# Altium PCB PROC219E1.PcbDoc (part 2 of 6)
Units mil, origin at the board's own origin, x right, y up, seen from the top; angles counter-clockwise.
Board outline 5354.33 x 5354.33 mil, 4 copper layers (Top Layer, Inner Layer 1, Inner Layer 2, Bottom Layer), stack 62.449 mil thick; 579 components, 299 nets, 1709 pads, 802 vias.
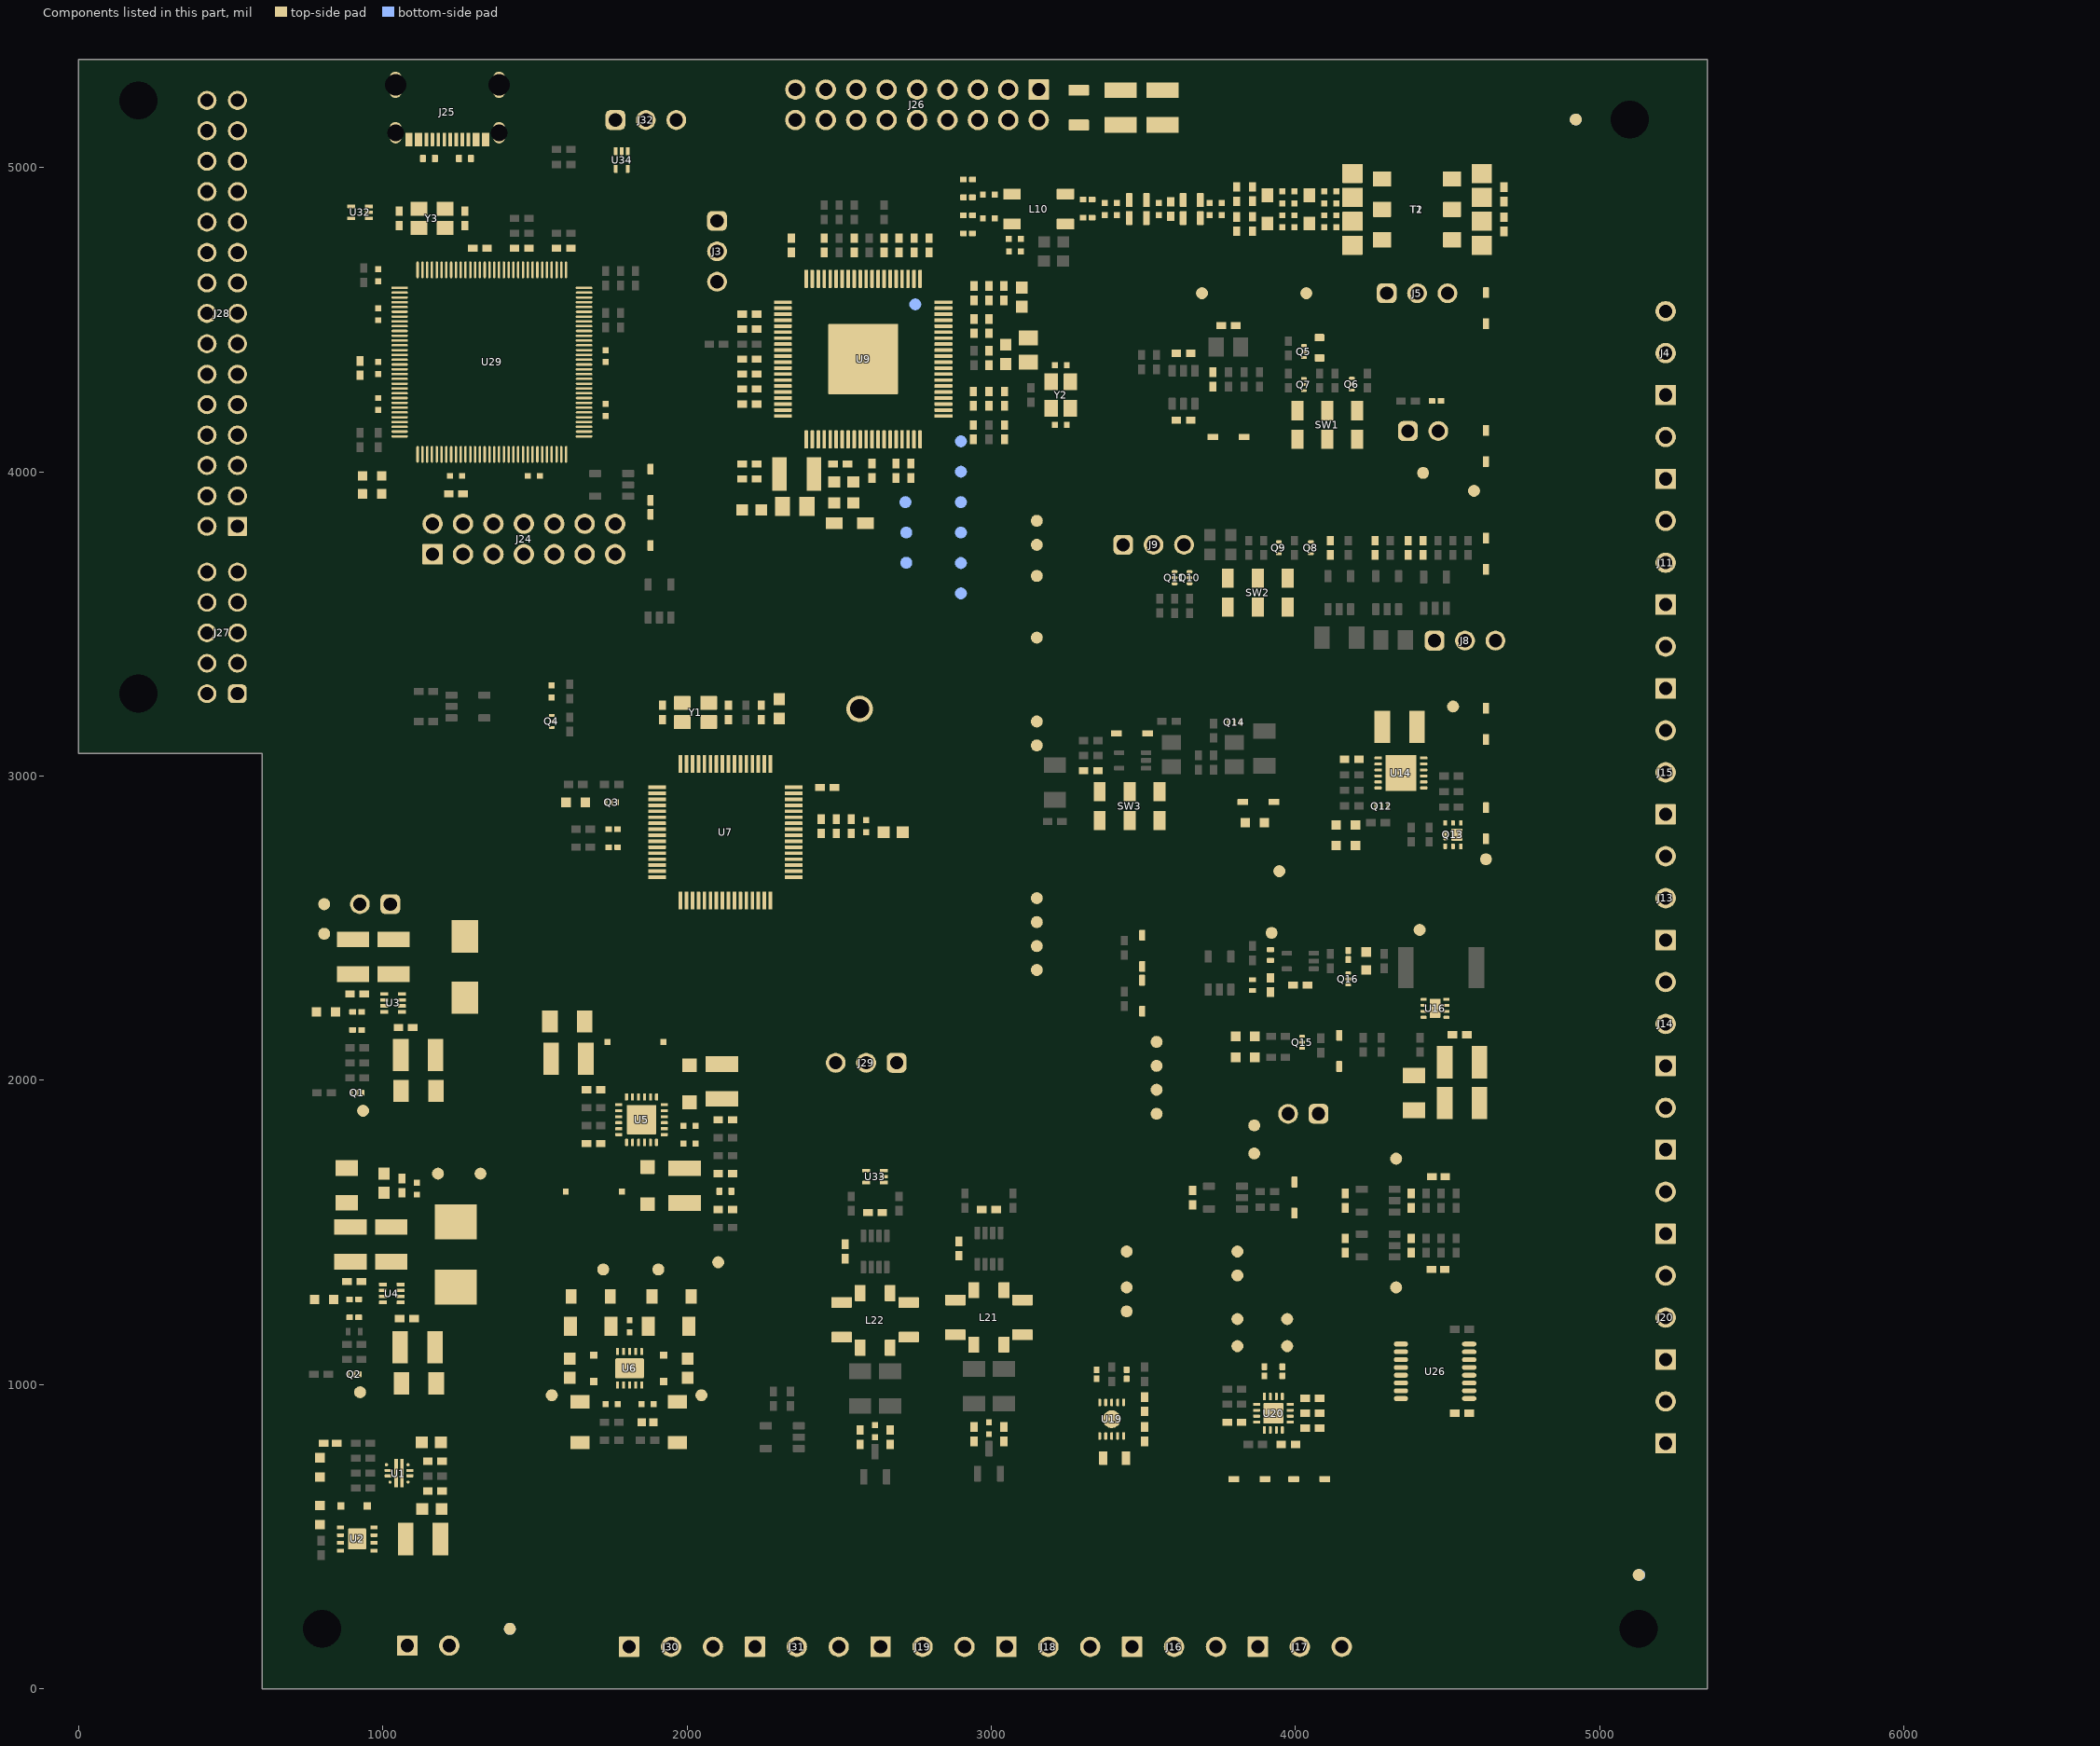
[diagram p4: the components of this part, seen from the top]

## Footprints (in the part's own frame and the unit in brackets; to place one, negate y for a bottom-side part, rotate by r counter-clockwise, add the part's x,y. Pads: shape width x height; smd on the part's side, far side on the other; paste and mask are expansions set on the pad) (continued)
DNT0012B-MFG [mm]
  rrect40% 0.6x0.25 smd paste+0 mask+0: 1(-1.9,1.25) 2(-1.9,0.75) 3(-1.9,0.25) 4(-1.9,-0.25) 5(-1.9,-0.75) 6(-1.9,-1.25) 7(1.9,-1.25) 8(1.9,-0.75) 9(1.9,-0.25) 10(1.9,0.25) 11(1.9,0.75) 12(1.9,1.25)
  rrect4% 2.6x3 smd paste-1000 mask+0: 13(0,0)
  silkscreen extent -2.32,-2.05 2.05,2.57, body extent -2.3,-2.15 2.3,2.15, height 0.25
DQK0006C [mm] "WSON"
  rrect12% 0.9x0.86 on Top Paste: 0(0,0.325)
  rrect34% 0.7x0.29 on Top Paste: 0(0.095,-0.65)
  rrect33% 0.45x0.3 smd: 1(-0.975,0.65) 2(-0.975,0) 3(-0.975,-0.65) 4(0.975,-0.65) 5(0.975,0) 6(0.975,0.65)
  rrect33% 0.75x0.3 smd paste-0.15: 7(0.095,-0.65)
  rrect11% 1x0.95 smd paste-0.5: 8(0,0.325)
  silkscreen extent -1.15,-1.15 1.15,1.15, body extent -1,-1 1,1, height 0.82
DRB0008A [mm] "VSON-8"
  rrect32% 0.6x0.31 smd: 1(-1.4,0.975) 2(-1.4,0.325) 3(-1.4,-0.325) 4(-1.4,-0.975) 5(1.4,-0.975) 6(1.4,-0.325) 7(1.4,0.325) 8(1.4,0.975)
  rrect7% 1.5x1.75 smd paste-0.75: 9(0,0)
  Top Layer region: -0.7,-0.875 -0.49,-0.875 -0.471,-0.879 -0.455,-0.89 -0.444,-0.906 -0.44,-0.925 -0.44,-0.925 -0.44,-1.65 -0.436,-1.669 -0.425,-1.685 -0.409,-1.696 -0.39,-1.7 -0.39,-1.7 -0.26,-1.7 -0.241,-1.696 -0.225,-1.685 -0.214,-1.669 -0.21,-1.65 -0.21,-1.65 -0.21,-0.925 -0.206,-0.906 -0.195,-0.89 -0.179,-0.879 -0.16,-0.875 -0.16,-0.875 0.16,-0.875 0.179,-0.879 0.195,-0.89 0.206,-0.906 0.21,-0.925 0.21,-0.925 0.21,-1.65 0.21,-1.65 0.214,-1.669 0.225,-1.685 0.241,-1.696 0.26,-1.7 0.26,-1.7 0.39,-1.7 0.409,-1.696 0.425,-1.685 0.436,-1.669 0.44,-1.65 0.44,-1.65 0.44,-0.925 0.444,-0.906 0.455,-0.89 0.471,-0.879 0.49,-0.875 0.49,-0.875 0.7,-0.875 0.719,-0.871 0.735,-0.86 0.746,-0.844 0.75,-0.825 0.75,-0.825 0.75,0.825 0.746,0.844 0.735,0.86 0.719,0.871 0.7,0.875 0.7,0.875 0.49,0.875 0.471,0.879 0.455,0.89 0.444,0.906 0.44,0.925 0.44,0.925 0.44,1.65 0.436,1.669 0.425,1.685 0.409,1.696 0.39,1.7 0.39,1.7 0.26,1.7 0.241,1.696 0.225,1.685 0.214,1.669 0.21,1.65 0.21,1.65 0.21,1.65 0.21,0.925 0.206,0.906 0.195,0.89 0.179,0.879 0.16,0.875 0.16,0.875 -0.16,0.875 -0.179,0.879 -0.195,0.89 -0.206,0.906 -0.21,0.925 -0.21,0.925 -0.21,1.65 -0.214,1.669 -0.225,1.685 -0.241,1.696 -0.26,1.7 -0.26,1.7 -0.39,1.7 -0.409,1.696 -0.425,1.685 -0.436,1.669 -0.44,1.65 -0.44,1.65 -0.44,0.925 -0.444,0.906 -0.455,0.89 -0.471,0.879 -0.49,0.875 -0.49,0.875 -0.7,0.875 -0.719,0.871 -0.735,0.86 -0.746,0.844 -0.75,0.825 -0.75,0.825 -0.75,-0.825 -0.746,-0.844 -0.735,-0.86 -0.719,-0.871 -0.7,-0.875
  silkscreen extent -1.73,-1.73 1.73,1.73, body extent -1.5,-1.5 1.5,1.5, height 0.77
DRC0010V-MFG [mm]
  rrect42% 0.6x0.24 smd paste+0 mask+0: 1(-1.4,1) 2(-1.4,0.5) 3(-1.4,0) 4(-1.4,-0.5) 5(-1.4,-1) 6(1.4,-1) 7(1.4,-0.5) 8(1.4,0) 9(1.4,0.5) 10(1.4,1)
  round 1.485 smd paste-1000 mask+0: 11(0,0)
  Top Layer region: -0.825,1.1 -0.818,1.125 -0.8,1.143 -0.775,1.15 -0.775,1.15 -0.375,1.15 -0.375,1.65 -0.368,1.675 -0.35,1.693 -0.325,1.7 -0.325,1.7 -0.175,1.7 -0.156,1.696 -0.14,1.685 -0.129,1.669 -0.125,1.65 -0.125,1.65 -0.125,1.15 0.125,1.15 0.125,1.65 0.129,1.669 0.14,1.685 0.156,1.696 0.175,1.7 0.175,1.7 0.325,1.7 0.35,1.693 0.368,1.675 0.375,1.65 0.375,1.65 0.375,1.15 0.775,1.15 0.8,1.143 0.818,1.125 0.825,1.1 0.825,1.1 0.825,-1.1 0.818,-1.125 0.8,-1.143 0.775,-1.15 0.775,-1.15 0.375,-1.15 0.375,-1.65 0.368,-1.675 0.35,-1.693 0.325,-1.7 0.325,-1.7 0.175,-1.7 0.156,-1.696 0.14,-1.685 0.129,-1.669 0.125,-1.65 0.125,-1.65 0.125,-1.15 -0.125,-1.15 -0.125,-1.65 -0.129,-1.669 -0.14,-1.685 -0.156,-1.696 -0.175,-1.7 -0.175,-1.7 -0.325,-1.7 -0.35,-1.693 -0.368,-1.675 -0.375,-1.65 -0.375,-1.65 -0.375,-1.15 -0.775,-1.15 -0.8,-1.143 -0.818,-1.125 -0.825,-1.1 -0.825,-1.1
  silkscreen extent -2.37,-1.55 1.55,1.55, body extent -1.8,-1.8 1.8,1.8, height 0.25
DRL0005A [mm] "SOTFL, 5-Flat Leads, Body 1.2x1.6x0.6mm, Pitch 0.5mm, TI recommended"
  rrect33% 0.67x0.3 smd: 1(-0.74,0.5) 2(-0.74,0) 3(-0.74,-0.5) 4(0.74,-0.5) 5(0.74,0.5)
  silkscreen extent -0.9,-0.95 0.5,0.95, body extent -0.85,-0.85 0.85,0.85, height 0.62
DRL0008A [mm] "SOT-5X3-8"
  rrect33% 0.67x0.3 smd: 1(-0.74,0.75) 2(-0.74,0.25) 3(-0.74,-0.25) 4(-0.74,-0.75) 5(0.74,-0.75) 6(0.74,-0.25) 7(0.74,0.25) 8(0.74,0.75)
  body extent -0.8,-1.05 0.8,1.05, height 0.61
DSC0010J [mm] "WSON-10"
  rrect42% 0.6x0.24 smd: 1(-1.4,1) 2(-1.4,0.5) 3(-1.4,0) 4(-1.4,-0.5) 5(-1.4,-1) 6(1.4,-1) 7(1.4,-0.5) 8(1.4,0) 9(1.4,0.5) 10(1.4,1)
  rrect12% 1.65x2.4 smd paste-1 mask-2: 11(0,0)
  Top Layer region: -0.375,-1.65 -0.375,-1.2 -0.775,-1.2 -0.794,-1.196 -0.81,-1.185 -0.821,-1.169 -0.825,-1.15 -0.825,-1.15 -0.825,1.15 -0.821,1.169 -0.81,1.185 -0.794,1.196 -0.775,1.2 -0.775,1.2 -0.375,1.2 -0.375,1.65 -0.371,1.669 -0.36,1.685 -0.344,1.696 -0.325,1.7 -0.325,1.7 -0.325,1.7 -0.175,1.7 -0.175,1.7 -0.156,1.696 -0.14,1.685 -0.129,1.669 -0.125,1.65 -0.125,1.65 -0.125,1.2 0.125,1.2 0.125,1.65 0.129,1.669 0.14,1.685 0.156,1.696 0.175,1.7 0.175,1.7 0.175,1.7 0.325,1.7 0.325,1.7 0.344,1.696 0.36,1.685 0.371,1.669 0.375,1.65 0.375,1.65 0.375,1.2 0.775,1.2 0.794,1.196 0.81,1.185 0.821,1.169 0.825,1.15 0.825,1.15 0.825,-1.15 0.821,-1.169 0.81,-1.185 0.794,-1.196 0.775,-1.2 0.775,-1.2 0.375,-1.2 0.375,-1.65 0.371,-1.669 0.36,-1.685 0.344,-1.696 0.325,-1.7 0.325,-1.7 0.175,-1.7 0.156,-1.696 0.14,-1.685 0.129,-1.669 0.125,-1.65 0.125,-1.65 0.125,-1.2 -0.125,-1.2 -0.125,-1.65 -0.129,-1.669 -0.14,-1.685 -0.156,-1.696 -0.175,-1.7 -0.175,-1.7 -0.325,-1.7 -0.344,-1.696 -0.36,-1.685 -0.371,-1.669 -0.375,-1.65
  body extent -1.5,-1.5 1.5,1.5, height 0.8
DSG0008A-MFG [mm]
  rrect40% 0.5x0.25 smd paste+0 mask+0: 1(-0.95,0.75) 2(-0.95,0.25) 3(-0.95,-0.25) 4(-0.95,-0.75) 5(0.95,-0.75) 6(0.95,-0.25) 7(0.95,0.25) 8(0.95,0.75)
  rrect11% 0.9x1.6 smd paste-1000 mask+0: 9(0,0)
  silkscreen extent -1.88,-1.39 1,1.4, body extent -1.3,-1.15 1.3,1.15, height 0.25
DYF0002A-CA-MFG [mm] "Recommended Land Pattern"
  rrect20% 0.9x0.5 smd paste+0 mask+0: 1(-1.3,0) 2(1.3,0)
  silkscreen extent -0.9,-0.7 0.9,0.7, body extent -1.85,-0.8 1.85,0.8, height 0.25
DYF0002A-MFG [mm]
  rrect20% 0.9x0.5 smd paste+0 mask+0: 1(-1.3,0) 2(1.3,0)
  silkscreen extent -2.27,-0.7 0.9,0.7, body extent -1.85,-0.8 1.85,0.8, height 0.25
ESD_Overlay_Large [mil]
  silkscreen extent -254,-219 250,219
FCC_disclaimer [mil]
Fiducial10-20 [mm]
  round 1 smd mask+0.5: 1(0,0)
  Top Layer keep-out circle w1.178: c0,0 r0.5
FP-150060AS75000_0603-MFG [mm] "Recommended Land Pattern"
  rrect13% 0.8x0.8 smd paste+0 mask+0: 1(-0.8,0) 2(0.8,0)
  silkscreen extent -1.88,-0.45 0,0.45, body extent -1.3,-0.55 1.3,0.55, height 0.25
FP-61301421121_HDR14-MFG [mm]
  rrect6% 1.7x1.7 hole 1.1 paste-2539.97 mask+0: 1(-7.62,-1.27)
  round 1.7 hole 1.1 paste-2539.97 mask+0: 2(-7.62,1.27) 3(-5.08,-1.27) 4(-5.08,1.27) 5(-2.54,-1.27) 6(-2.54,1.27) 7(0,-1.27) 8(0,1.27) 9(2.54,-1.27) 10(2.54,1.27) 11(5.08,-1.27) 12(5.08,1.27) 13(7.62,-1.27) 14(7.62,1.27)
  silkscreen extent -9.76,-2.62 9.04,2.62, body extent -9.14,-2.72 9.14,2.72, height 0.25
FP-61301821121_HDR18-MFG [mm] "Recommended Land Pattern"
  rrect6% 1.7x1.7 hole 1.1 paste-2539.97 mask+0: 1(-10.16,-1.27)
  round 1.7 hole 1.1 paste-2539.97 mask+0: 2(-10.16,1.27) 3(-7.62,-1.27) 4(-7.62,1.27) 5(-5.08,-1.27) 6(-5.08,1.27) 7(-2.54,-1.27) 8(-2.54,1.27) 9(0,-1.27) 10(0,1.27) 11(2.54,-1.27) 12(2.54,1.27) 13(5.08,-1.27) 14(5.08,1.27) 15(7.62,-1.27) 16(7.62,1.27) 17(10.16,-1.27) 18(10.16,1.27)
  silkscreen extent -11.58,-3.22 11.58,2.62, body extent -11.68,-2.72 11.68,2.72, height 0.25
FP-691214110002S_HDR2-MFG [mm]
  rrect6% 1.7x1.7 hole 1.1 paste-2539.97 mask+0: 1(-2.05,-0.15)
  round 1.7 hole 1.1 paste-2539.97 mask+0: 2(1.45,-0.15)
  silkscreen extent -4.65,-3.7 4,3.7, body extent -4.1,-3.8 4.1,3.8, height 0.25
FP-691214110003S_CONN_TERM_BLK_3-MFG [mm] "Recommended Land Pattern"
  rrect6% 1.7x1.7 hole 1.1 paste-2539.97 mask+0: 1(-3.5,-0.15)
  round 1.7 hole 1.1 paste-2539.97 mask+0: 2(0,-0.15) 3(3.5,-0.15)
  silkscreen extent -5.45,-3.7 6.05,4.52, body extent -5.55,-3.8 6.15,3.8, height 0.25
FP-830103622909_SMT_CRYSTAL_3MM4_2MM7-MFG [mm] "Recommended Land Pattern"
  rrect9% 1.4x1.15 smd paste+0 mask+0: 1(-1.1,-0.8) 2(1.1,-0.8) 3(1.1,0.8) 4(-1.1,0.8)
  silkscreen extent -1.23,-2.05 0,1.35, body extent -1.9,-1.48 1.9,1.48, height 0.25
FP-ABM8W-25.0000MHZ-8-D1X-T3_SMD4-MFG [mm] "Recommended Land Pattern"
  rrect9% 1.4x1.15 smd paste+0 mask+0: 1(-1.1,-0.8) 2(1.1,-0.8) 3(1.1,0.8) 4(-1.1,0.8)
  silkscreen extent -1.65,-2.33 1.65,1.75, body extent -1.9,-1.48 1.9,1.48, height 0.25
FP-ACT45B-101-2P-TL003_SMT_4MM5_3MM2-MFG [mm]
  rrect11% 1.35x0.9 smd paste+0 mask+0: 1(-2.275,1.25) 2(-2.275,-1.25) 3(2.275,-1.25) 4(2.275,1.25)
  silkscreen extent -2.82,-1.7 2.35,2.22, body extent -3.05,-1.8 3.05,1.8, height 0.25
FP-CRCW12060000Z0EAC_1206-MFG [mm]
  rrect11% 0.9x1.7 smd paste+0 mask+0: 1(-1.45,0) 2(1.45,0)
  silkscreen extent -0.63,-0.82 0.63,0.82, body extent -2,-0.95 2,0.95, height 0.25
FP-CRG0402ZR_0402-IPC_C [mil]
  rrect21% 22.03x18.6 smd paste+0 mask+0: 1(-14.81,0) 2(14.81,0)
  silkscreen extent -26,-27 26,27, body extent -30,-15 30,15, height 10
FP-DLW43SH110XK2L_1812-MFG [mm] "Recommended Land Pattern"
  rrect11% 1.45x0.9 smd paste+0 mask+0: 1(-2.225,-1.25) 2(2.225,-1.25) 3(2.225,1.25) 4(-2.225,1.25)
  silkscreen extent -2.66,-2.2 2.35,1.7, body extent -3.05,-1.8 3.05,1.8, height 0.25
FP-IS31CG5317-LQLS3_LQFP80-MFG [mm] "Recommended Land Pattern"
  rrect33% 1.5x0.3 smd paste+0 mask+0: 1(-6.7,4.75) 2(-6.7,4.25) 3(-6.7,3.75) 4(-6.7,3.25) 5(-6.7,2.75) 6(-6.7,2.25) 7(-6.7,1.75) 8(-6.7,1.25) 9(-6.7,0.75) 10(-6.7,0.25) 11(-6.7,-0.25) 12(-6.7,-0.75) 13(-6.7,-1.25) 14(-6.7,-1.75) 15(-6.7,-2.25) 16(-6.7,-2.75) 17(-6.7,-3.25) 18(-6.7,-3.75) 19(-6.7,-4.25) 20(-6.7,-4.75) 41(6.7,-4.75) 42(6.7,-4.25) 43(6.7,-3.75) 44(6.7,-3.25) 45(6.7,-2.75) 46(6.7,-2.25) 47(6.7,-1.75) 48(6.7,-1.25) 49(6.7,-0.75) 50(6.7,-0.25) 51(6.7,0.25) 52(6.7,0.75) 53(6.7,1.25) 54(6.7,1.75) 55(6.7,2.25) 56(6.7,2.75) 57(6.7,3.25) 58(6.7,3.75) 59(6.7,4.25) 60(6.7,4.75)
  rrect33% 0.3x1.5 smd paste+0 mask+0: 21(-4.75,-6.7) 22(-4.25,-6.7) 23(-3.75,-6.7) 24(-3.25,-6.7) 25(-2.75,-6.7) 26(-2.25,-6.7) 27(-1.75,-6.7) 28(-1.25,-6.7) 29(-0.75,-6.7) 30(-0.25,-6.7) 31(0.25,-6.7) 32(0.75,-6.7) 33(1.25,-6.7) 34(1.75,-6.7) 35(2.25,-6.7) 36(2.75,-6.7) 37(3.25,-6.7) 38(3.75,-6.7) 39(4.25,-6.7) 40(4.75,-6.7) 61(4.75,6.7) 62(4.25,6.7) 63(3.75,6.7) 64(3.25,6.7) 65(2.75,6.7) 66(2.25,6.7) 67(1.75,6.7) 68(1.25,6.7) 69(0.75,6.7) 70(0.25,6.7) 71(-0.25,6.7) 72(-0.75,6.7) 73(-1.25,6.7) 74(-1.75,6.7) 75(-2.25,6.7) 76(-2.75,6.7) 77(-3.25,6.7) 78(-3.75,6.7) 79(-4.25,6.7) 80(-4.75,6.7)
  rrect2% 5.85x5.85 smd paste-1000 mask+0: 81(0,0)
  silkscreen extent -6.82,-6.1 6.1,6.1, body extent -7.55,-7.55 7.55,7.55, height 0.25
FP-JS202011JCQN-MFG [mm]
  rect 1x1.6 smd paste+0 mask+0: 1(-2.5,-1.2) 2(0,-1.2) 3(2.5,-1.2) 5(-2.5,1.2) 6(0,1.2) 7(2.5,1.2)
  silkscreen extent -4.5,-2.72 4.5,1.8, body extent -4.6,-2.1 4.6,2.1, height 0.25
"FP-LQM21PN4R7MGRD_0805 (2012)-MFG" [mm] "Recommended Land Pattern"
  rrect10% 1.15x1 smd paste+0 mask+0: 1(-1.175,0) 2(1.175,0)
  silkscreen extent -0.23,-0.7 0.23,0.7, body extent -1.85,-0.8 1.85,0.8, height 0.25
"FP-LQW18ANR27G80D_0603 (1608)-MFG" [mm] "Recommended Land Pattern"
  rrect18% 0.57x1.15 smd paste+0 mask+0: 1(-0.715,0) 2(0.715,0)
  silkscreen extent -0.06,-0.55 0.06,0.55, body extent -1.1,-0.67 1.1,0.67, height 0.25
FP-PWB3010LC_SMD6-MFG [mm] "Recommended Land Pattern"
  rrect8% 1.52x1.27 smd paste+0 mask+0: 1(-2.925,2.54) 2(-2.925,0) 3(-2.925,-2.54) 4(2.925,-2.54) 5(2.925,0) 6(2.925,2.54)
  silkscreen extent -3.48,-3.34 3.48,4.32, body extent -3.78,-3.44 3.78,3.44, height 0.25
FP-RC0402FR-1391KL_0402-IPC_A [mil]
  rrect15% 28.16x26.48 smd paste+0 mask+0: 1(-18.84,0) 2(18.84,0)
  silkscreen extent -33,-29 33,29, body extent -41,-21 41,21, height 10
FP-RMCF0402FT5K10_0402-MFG [mm]
  rrect20% 0.5x0.6 smd paste+0 mask+0: 1(-0.5,0) 2(0.5,0)
  silkscreen extent -0.55,-0.7 0.55,0.7, body extent -0.85,-0.4 0.85,0.4, height 0.25
FP-RN242SMT2R_EMD2-MFG [mm] "Recommended Land Pattern"
  rrect17% 0.6x0.8 smd paste+0 mask+0: 1(-0.85,0) 2(0.85,0)
  silkscreen extent -0.97,-0.92 0.18,0.43, body extent -0.8,-0.4 0.8,0.4, height 0.7
FP-SDR10EZPF1200_0805-MFG [mm] "Recommended Land Pattern"
  rrect14% 0.7x1.15 smd paste+0 mask+0: 1(-0.95,0) 2(0.95,0)
  silkscreen extent -0.23,-0.67 0.23,0.67, body extent -1,-0.63 1,0.63, height 0.65
FP-SS2040FL_R1_00001_SOD123FL-MFG [mm]
  rrect9% 1.15x1.22 smd paste+0 mask+0: 1(-1.55,0) 2(1.55,0)
  silkscreen extent -2.82,-0.95 0.6,0.95, body extent -2.22,-1.05 2.22,1.05, height 0.25
FP-SSW-115-01-G-D_CONN_RCPT30-MFG [mm] "Recommended Land Pattern"
  rrect6% 1.59x1.59 hole 1.1 paste-2539.97 mask+0: 1(17.78,-1.27)
  round 1.59 hole 1.1 paste-2539.97 mask+0: 2(17.78,1.27) 3(15.24,-1.27) 4(15.24,1.27) 5(12.7,-1.27) 6(12.7,1.27) 7(10.16,-1.27) 8(10.16,1.27) 9(7.62,-1.27) 10(7.62,1.27) 11(5.08,-1.27) 12(5.08,1.27) 13(2.54,-1.27) 14(2.54,1.27) 15(0,-1.27) 16(0,1.27) 17(-2.54,-1.27) 18(-2.54,1.27) 19(-5.08,-1.27) 20(-5.08,1.27) 21(-7.62,-1.27) 22(-7.62,1.27) 23(-10.16,-1.27) 24(-10.16,1.27) 25(-12.7,-1.27) 26(-12.7,1.27) 27(-15.24,-1.27) 28(-15.24,1.27) 29(-17.78,-1.27) 30(-17.78,1.27)
  silkscreen extent -19.37,-3.44 19.37,2.54, body extent -19.31,-2.48 19.31,2.47, height 8.64
FP-TNPW0402150RBEED_0402-MFG [mm]
  rrect25% 0.4x0.6 smd paste+0 mask+0: 1(-0.45,0) 2(0.45,0)
  silkscreen extent -0.53,-0.67 0.53,0.67, body extent -0.75,-0.4 0.75,0.4, height 0.25
FP-USB4215-03-A_CONN_USB-MFG [mm]
  rrect100% 1x1.8 hole 1.4 slot 0.6 at 0 deg paste-2539.97 mask+0: 1(-4.32,2.85) 2(4.32,2.85)
  rrect100% 1x2.2 hole 1.8 slot 0.6 at 0 deg paste-2539.97 mask+0: 3(-4.32,-1.15) 4(4.32,-1.15)
  rrect17% 0.6x1.15 smd paste+0 mask+0: A1-B12(-3.2,3.425) A4-B9(-2.4,3.425) B1-A12(3.2,3.425) B4-A9(2.4,3.425)
  rrect33% 0.3x1.15 smd paste+0 mask+0: A5(-1.25,3.425) A6(-0.25,3.425) A7(0.25,3.425) A8(1.25,3.425) B5(1.75,3.425) B6(0.75,3.425) B7(-0.75,3.425) B8(-1.75,3.425)
  silkscreen extent -4.59,-3.37 4.59,4.67, body extent -4.92,-3.47 4.92,4.1, height 0.25
FP-WR04X6802FTL_0402-MFG [mm]
  rrect20% 0.5x0.6 smd paste+0 mask+0: 1(-0.5,0) 2(0.5,0)
  silkscreen extent -0.51,-0.68 0.5,0.7, body extent -0.95,-0.5 0.95,0.5, height 0.25
FP-ZA9756-AED_SMD8-MFG [mm] "Recommended Land Pattern"
  rrect6% 1.7x1.6 smd paste+0 mask+0: 1(-5.4,3) 2(-5.4,1) 3(-5.4,-1) 4(-5.4,-3) 5(5.4,-3) 6(5.4,-1) 7(5.4,1) 8(5.4,3)
  silkscreen extent -5.47,-5.15 4.18,5.15, body extent -6.35,-5.25 6.35,5.25, height 0.25
Keystone5011 [mil] "Keystone Multipurpose loops"
  round 87 hole 63: 1(0,0)
  silkscreen extent -70,-70 70,70, body extent -63,-63 63,62, height 319
NDK_NX3225GA [mm] "NDK"
  rect 1.2x1.4 smd: 1(-0.8,1.1) 2(-0.8,-1.1) 3(0.8,-1.1) 4(0.8,1.1)
  silkscreen extent -1.9,-0.1 1.4,2, body extent -1.3,-1.65 1.3,1.65, height 0.9
Net-Tie_10mil [mil] "10mil net tie, no solder mask opening, no solder paste"
  rect 10x10 on Mid1 paste-5 mask-5: 1(-10,0) 2(10,0)
  Inner Layer 1 region: -6,5 6,5 6,-5 -6,-5
NPTH125mil#1 [mil]
  round 120 hole 125 unplated mask+15: 1(0,0)
NPTH125mil#2 [mil]
  round 120 hole 125 unplated mask+15: 1(-29.53,39.37)
NPTH125mil#3 [mil]
  round 120 hole 125 unplated mask+15: 1(-59.06,0)
PDT0128A [mm] "Thin QFP, 128-Leads, Body 14x14mm, Pitch 0.4mm"
  oval 1.4x0.2 smd: 1(-7.7,6.2) 2(-7.7,5.8) 3(-7.7,5.4) 4(-7.7,5) 5(-7.7,4.6) 6(-7.7,4.2) 7(-7.7,3.8) 8(-7.7,3.4) 9(-7.7,3) 10(-7.7,2.6) 11(-7.7,2.2) 12(-7.7,1.8) 13(-7.7,1.4) 14(-7.7,1) 15(-7.7,0.6) 16(-7.7,0.2) 17(-7.7,-0.2) 18(-7.7,-0.6) 19(-7.7,-1) 20(-7.7,-1.4) 21(-7.7,-1.8) 22(-7.7,-2.2) 23(-7.7,-2.6) 24(-7.7,-3) 25(-7.7,-3.4) 26(-7.7,-3.8) 27(-7.7,-4.2) 28(-7.7,-4.6) 29(-7.7,-5) 30(-7.7,-5.4) 31(-7.7,-5.8) 32(-7.7,-6.2) 65(7.7,-6.2) 66(7.7,-5.8) 67(7.7,-5.4) 68(7.7,-5) 69(7.7,-4.6) 70(7.7,-4.2) 71(7.7,-3.8) 72(7.7,-3.4) 73(7.7,-3) 74(7.7,-2.6) 75(7.7,-2.2) 76(7.7,-1.8) 77(7.7,-1.4) 78(7.7,-1) 79(7.7,-0.6) 80(7.7,-0.2) 81(7.7,0.2) 82(7.7,0.6) 83(7.7,1) 84(7.7,1.4) 85(7.7,1.8) 86(7.7,2.2) 87(7.7,2.6) 88(7.7,3) 89(7.7,3.4) 90(7.7,3.8) 91(7.7,4.2) 92(7.7,4.6) 93(7.7,5) 94(7.7,5.4) 95(7.7,5.8) 96(7.7,6.2)
  oval 0.2x1.4 smd: 33(-6.2,-7.7) 34(-5.8,-7.7) 35(-5.4,-7.7) 36(-5,-7.7) 37(-4.6,-7.7) 38(-4.2,-7.7) 39(-3.8,-7.7) 40(-3.4,-7.7) 41(-3,-7.7) 42(-2.6,-7.7) 43(-2.2,-7.7) 44(-1.8,-7.7) 45(-1.4,-7.7) 46(-1,-7.7) 47(-0.6,-7.7) 48(-0.2,-7.7) 49(0.2,-7.7) 50(0.6,-7.7) 51(1,-7.7) 52(1.4,-7.7) 53(1.8,-7.7) 54(2.2,-7.7) 55(2.6,-7.7) 56(3,-7.7) 57(3.4,-7.7) 58(3.8,-7.7) 59(4.2,-7.7) 60(4.6,-7.7) 61(5,-7.7) 62(5.4,-7.7) 63(5.8,-7.7) 64(6.2,-7.7) 97(6.2,7.7) 98(5.8,7.7) 99(5.4,7.7) 100(5,7.7) 101(4.6,7.7) 102(4.2,7.7) 103(3.8,7.7) 104(3.4,7.7) 105(3,7.7) 106(2.6,7.7) 107(2.2,7.7) 108(1.8,7.7) 109(1.4,7.7) 110(1,7.7) 111(0.6,7.7) 112(0.2,7.7) 113(-0.2,7.7) 114(-0.6,7.7) 115(-1,7.7) 116(-1.4,7.7) 117(-1.8,7.7) 118(-2.2,7.7) 119(-2.6,7.7) 120(-3,7.7) 121(-3.4,7.7) 122(-3.8,7.7) 123(-4.2,7.7) 124(-4.6,7.7) 125(-5,7.7) 126(-5.4,7.7) 127(-5.8,7.7) 128(-6.2,7.7)
  silkscreen extent -7.7,-6.3 6.3,6.99, body extent -8,-8 8,8, height 1.07
PM0064A-MFG [mm]
  rrect33% 1.5x0.3 smd paste+0 mask+0: 1(-5.7,3.75) 2(-5.7,3.25) 3(-5.7,2.75) 4(-5.7,2.25) 5(-5.7,1.75) 6(-5.7,1.25) 7(-5.7,0.75) 8(-5.7,0.25) 9(-5.7,-0.25) 10(-5.7,-0.75) 11(-5.7,-1.25) 12(-5.7,-1.75) 13(-5.7,-2.25) 14(-5.7,-2.75) 15(-5.7,-3.25) 16(-5.7,-3.75) 33(5.7,-3.75) 34(5.7,-3.25) 35(5.7,-2.75) 36(5.7,-2.25) 37(5.7,-1.75) 38(5.7,-1.25) 39(5.7,-0.75) 40(5.7,-0.25) 41(5.7,0.25) 42(5.7,0.75) 43(5.7,1.25) 44(5.7,1.75) 45(5.7,2.25) 46(5.7,2.75) 47(5.7,3.25) 48(5.7,3.75)
  rrect33% 0.3x1.5 smd paste+0 mask+0: 17(-3.75,-5.7) 18(-3.25,-5.7) 19(-2.75,-5.7) 20(-2.25,-5.7) 21(-1.75,-5.7) 22(-1.25,-5.7) 23(-0.75,-5.7) 24(-0.25,-5.7) 25(0.25,-5.7) 26(0.75,-5.7) 27(1.25,-5.7) 28(1.75,-5.7) 29(2.25,-5.7) 30(2.75,-5.7) 31(3.25,-5.7) 32(3.75,-5.7) 49(3.75,5.7) 50(3.25,5.7) 51(2.75,5.7) 52(2.25,5.7) 53(1.75,5.7) 54(1.25,5.7) 55(0.75,5.7) 56(0.25,5.7) 57(-0.25,5.7) 58(-0.75,5.7) 59(-1.25,5.7) 60(-1.75,5.7) 61(-2.25,5.7) 62(-2.75,5.7) 63(-3.25,5.7) 64(-3.75,5.7)
  silkscreen extent -7.12,-5.1 5.1,5.1, body extent -6.55,-6.55 6.55,6.55, height 0.25
PW0016A_L [mm] "TSOP, 16-Leads, Body 5x4.4mm, Pitch 0.65mm, IPC High Density"
  oval 1.2x0.4 smd: 1(-2.85,2.275) 2(-2.85,1.625) 3(-2.85,0.975) 4(-2.85,0.325) 5(-2.85,-0.325) 6(-2.85,-0.975) 7(-2.85,-1.625) 8(-2.85,-2.275) 9(2.85,-2.275) 10(2.85,-1.625) 11(2.85,-0.975) 12(2.85,-0.325) 13(2.85,0.325) 14(2.85,0.975) 15(2.85,1.625) 16(2.85,2.275)
  silkscreen extent -2,-2.55 1.85,2.55, body extent -3.21,-2.5 3.21,2.5, height 1
RGE0024B [mm] "QFN, 24-Leads, Body 4x4mm, Pitch 0.5mm, Thermal Pad 2.45x2.45mm, TI Recommended"
  rrect40% 0.6x0.25 smd: 1(-1.9,1.25) 2(-1.9,0.75) 3(-1.9,0.25) 4(-1.9,-0.25) 5(-1.9,-0.75) 6(-1.9,-1.25) 13(1.9,-1.25) 14(1.9,-0.75) 15(1.9,-0.25) 16(1.9,0.25) 17(1.9,0.75) 18(1.9,1.25)
  rrect40% 0.25x0.6 smd: 7(-1.25,-1.9) 8(-0.75,-1.9) 9(-0.25,-1.9) 10(0.25,-1.9) 11(0.75,-1.9) 12(1.25,-1.9) 19(1.25,1.9) 20(0.75,1.9) 21(0.25,1.9) 22(-0.25,1.9) 23(-0.75,1.9) 24(-1.25,1.9)
  rrect9% 1.08x1.08 on Top Paste: 25(-0.64,0.64) 25(-0.64,-0.64) 25(0.64,0.64) 25(0.64,-0.64)
  rrect4% 2.45x2.45 smd paste-1.225: 25(0,0)
  silkscreen extent -2.22,-2.22 2.22,2.22, body extent -2,-2 2,2, height 1
RGT0016C-MFG [mm]
  rrect42% 0.6x0.24 smd paste+0 mask+0: 1(-1.4,0.75) 2(-1.4,0.25) 3(-1.4,-0.25) 4(-1.4,-0.75) 9(1.4,-0.75) 10(1.4,-0.25) 11(1.4,0.25) 12(1.4,0.75)
  rrect42% 0.24x0.6 smd paste+0 mask+0: 5(-0.75,-1.4) 6(-0.25,-1.4) 7(0.25,-1.4) 8(0.75,-1.4) 13(0.75,1.4) 14(0.25,1.4) 15(-0.25,1.4) 16(-0.75,1.4)
  rrect6% 1.68x1.68 smd paste-1000 mask+0: 17(0,0)
  silkscreen extent -1.58,-1.55 1.55,2.02, body extent -1.8,-1.8 1.8,1.8, height 0.25
RPW0010A-MFG [mm]
  round 0.27 smd paste-1000 mask+0: 1(-1.05,0.7) 10(0.75,0.7)
  rrect40% 0.6x0.25 smd paste+0 mask+0: 2(-0.9,0.225) 3(-0.9,-0.225) 8(0.9,-0.225) 9(0.9,0.225)
  round 0.255 smd paste-1000 mask+0: 4(-0.75,-0.75) 7(0.75,-0.75)
  rrect33% 0.3x2.4 smd paste-1000 mask+0: 5(-0.25,0) 6(0.25,0)
  Top Layer region: -0.85,0.85 -0.85,1.15 -0.843,1.175 -0.825,1.193 -0.8,1.2 -0.8,1.2 -0.65,1.2 -0.631,1.196 -0.615,1.185 -0.604,1.169 -0.6,1.15 -0.6,1.15 -0.6,0.6 -0.604,0.581 -0.615,0.565 -0.631,0.554 -0.65,0.55 -0.65,0.55 -1.15,0.55 -1.169,0.554 -1.185,0.565 -1.196,0.581 -1.2,0.6 -1.2,0.6 -1.2,0.8 -1.193,0.825 -1.175,0.843 -1.15,0.85 -1.15,0.85
  Top Layer region: -0.85,-0.85 -0.85,-1.15 -0.846,-1.169 -0.835,-1.185 -0.819,-1.196 -0.8,-1.2 -0.8,-1.2 -0.65,-1.2 -0.631,-1.196 -0.615,-1.185 -0.604,-1.169 -0.6,-1.15 -0.6,-1.15 -0.6,-0.6 -0.604,-0.581 -0.615,-0.565 -0.631,-0.554 -0.65,-0.55 -0.65,-0.55 -1.15,-0.55 -1.169,-0.554 -1.185,-0.565 -1.196,-0.581 -1.2,-0.6 -1.2,-0.6 -1.2,-0.8 -1.196,-0.819 -1.185,-0.835 -1.169,-0.846 -1.15,-0.85 -1.15,-0.85
  Top Layer region: 0.85,-0.85 0.85,-1.15 0.846,-1.169 0.835,-1.185 0.819,-1.196 0.8,-1.2 0.8,-1.2 0.65,-1.2 0.631,-1.196 0.615,-1.185 0.604,-1.169 0.6,-1.15 0.6,-1.15 0.6,-0.6 0.604,-0.581 0.615,-0.565 0.631,-0.554 0.65,-0.55 0.65,-0.55 1.15,-0.55 1.169,-0.554 1.185,-0.565 1.196,-0.581 1.2,-0.6 1.2,-0.6 1.2,-0.8 1.196,-0.819 1.185,-0.835 1.169,-0.846 1.15,-0.85 1.15,-0.85
  Top Layer region: 0.85,0.85 0.85,1.15 0.846,1.169 0.835,1.185 0.819,1.196 0.8,1.2 0.8,1.2 0.65,1.2 0.631,1.196 0.615,1.185 0.604,1.169 0.6,1.15 0.6,1.15 0.6,0.6 0.604,0.581 0.615,0.565 0.631,0.554 0.65,0.55 0.65,0.55 1.15,0.55 1.169,0.554 1.185,0.565 1.196,0.581 1.2,0.6 1.2,0.6 1.2,0.8 1.196,0.819 1.185,0.835 1.169,0.846 1.15,0.85 1.15,0.85
  silkscreen extent -1.47,-1.58 1.05,1.58, body extent -1.3,-1.3 1.3,1.3, height 0.25
Samtec_SSW-105-01-x-D [mm] "Receptacle, 2.54mm, 5X2, TH"
  rrect50% 1.56x1.56 hole 1.1: 1(-5.08,1.27)
  round 1.56 hole 1.1: 2(-5.08,-1.27) 3(-2.54,1.27) 4(-2.54,-1.27) 5(0,1.27) 6(0,-1.27) 7(2.54,1.27) 8(2.54,-1.27) 9(5.08,1.27) 10(5.08,-1.27)
  silkscreen extent -6.9,-2.48 6.6,2.48, body extent -6.6,-2.48 6.6,2.48, height 8.51
SOD-123 [mm] "On Semi recommended land pattern"
  rect 0.915x1.22 smd: 1(-1.637,0) 2(1.637,0)
  silkscreen extent -2.74,-1.17 2.03,1.17, body extent -1.93,-0.9 1.93,0.9, height 1.35
SOD-323 [mm] "NXP recommended land pattern"
  rect 0.6x0.6 smd paste-0.05: 1(-1.1,0) 2(1.1,0)
  silkscreen extent -2.06,-0.86 1.53,0.86, body extent -1.3,-0.67 1.3,0.68, height 1.1
SOD-523 [mm] "NXP Semiconductor recommended land pattern, nominal STEP model"
  rect 0.8x0.6 smd paste-0.05: 1(-0.55,0) 2(0.55,0)
  silkscreen extent -1.65,-0.66 1.2,0.66, body extent -0.8,-0.4 0.8,0.4, height 0.72
TI_Horizontal_Overlay_Medium [mil]
TP_SM_1MM [mm] "1mm Test Point, SMT"
  round 1 smd paste-0.5: 1(0,0)
WCAP-CSGP_0402_L1W0.5H0.5 [mm] "Ceramic Capacitors, body 1x0.5mm"
  rect 0.5x0.5 smd: 1(-0.5,0) 2(0.5,0)
  body extent -0.5,-0.25 0.5,0.25, height 0.5
WCAP-CSGP_0603_L1.6W0.8H0.8_Reflow [mm] "Ceramic Capacitors, body 1.6x0.8mm"
  rect 0.8x0.8 smd: 1(-0.75,0) 2(0.75,0)
  body extent -0.8,-0.4 0.8,0.4, height 0.8
WCAP-CSRF_0402_L1W0.5H0.5 [mm] "Radio Frequency MLCC, body 1x0.5mm"
  rect 0.5x0.5 smd: 1(-0.5,0) 2(0.5,0)
  body extent -0.5,-0.25 0.5,0.25, height 0.5
WE-HC4 [mm] "Wurth Electronik recommended land pattern"
  rect 2.7x2.2 smd: 1(-2.55,0) 2(2.55,0)
  silkscreen extent -4.2,-4.2 4.2,4.2, body extent -3.65,-3.6 3.65,3.6, height 4
WE-LHMI_7050 [mm] "Wurth"
  rect 2.95x3.5 smd: 1(-2.725,0) 2(2.725,0)
  silkscreen extent -3.55,-3.55 3.55,3.55, body extent -3.8,-3.45 3.8,3.45, height 5
WE-MPSB_0805_L2W1.2H0.9 [mm] "SMD EMI Multilayer Power Suppression Bead, body 2.00x1.20mm"
  rect 1.4x1 smd: 1(-1.3,0) 2(1.3,0)
  body extent -1,-0.6 1,0.6, height 0.9
WE-PMCI_1210_L3.2W2.5H1.2 [mm] "Power Molded Chip Inductor, body 3.2x2.5mm"
  rect 1.2x2.8 smd: 1(-1.45,0) 2(1.45,0)
  silkscreen extent -0.5,-1.35 0.5,1.35, body extent -1.6,-1.25 1.6,1.25, height 1.2
WE-TPC-M1 [mm] "Wurth Elektronik recommended land pattern"
  rect 0.5x0.5 smd: 1(-2.35,0) 2(2.325,0)
  Top Layer region: 0.75,1.64 1.005,1.504 1.279,1.279 1.504,1.005 1.671,0.692 1.774,0.353 1.809,0 1.774,-0.353 1.671,-0.692 1.504,-1.005 1.279,-1.279 1.005,-1.504 0.75,-1.64 0.75,-2.65 2.75,-2.65 2.75,2.65 0.75,2.65
  Top Layer region: -0.75,1.64 -1.005,1.504 -1.279,1.279 -1.504,1.005 -1.671,0.692 -1.774,0.353 -1.809,0 -1.774,-0.353 -1.671,-0.692 -1.504,-1.005 -1.279,-1.279 -1.005,-1.504 -0.75,-1.64 -0.75,-2.65 -2.75,-2.65 -2.75,2.65 -0.75,2.65
  silkscreen extent -3,-3 3,3, body extent -2.5,-2.5 2.5,2.5, height 2
WEEE_Minimum [mil] "WEEElie bin"
  silkscreen extent -95,-172 99,104
WL-SMCW_GREEN [mm] "WURTH"
  rect 0.8x0.8 smd: 1(-0.8,0) 2(0.8,0)
  silkscreen extent -1.9,-0.8 1.2,0.8, body extent -0.85,-0.45 0.85,0.45, height 0.8
WL-SMCW_RED [mm] "WURTH"
  rect 0.8x0.8 smd: 1(-0.8,0) 2(0.8,0)
  silkscreen extent -1.9,-0.8 1.2,0.8, body extent -0.85,-0.45 0.85,0.45, height 0.8
Wurth_60900213421 [mil] "Shunt, 2.54mm, Black"
  round 1 on Mech3: 0(0,0)
  body extent -98,-648 98,-552, height 338
WURTH_61300211121 [mm] "Header, 2.54mm, 2x1, TH"
  rrect50% 1.65x1.65 hole 1.1: 1(-1.27,0)
  round 1.65 hole 1.1: 2(1.27,0)
  body extent -2.54,-1.27 2.54,1.27, height 8.54
WURTH_61300311121 [mm] "Header, 2.54mm, 3x1, TH"
  rrect50% 1.65x1.65 hole 1.1: 1(-2.54,0)
  round 1.65 hole 1.1: 2(0,0) 3(2.54,0)
  body extent -3.81,-1.27 3.81,1.27, height 8.54
YJK0003A [mm] "SMD, 3-Leads, Body 1.49x0.73mm"
  rrect50% 0.2x0.39 on Top Paste: 1(-0.525,0) 2(0,0) 3(0.525,0)
  rrect80% 0.25x0.49 smd paste-0.15 mask-0.05: 1(-0.5,0) 2(0,0) 3(0.5,0)
  silkscreen extent -0.9,-0.5 0.9,0.5, body extent -0.75,-0.37 0.74,0.36, height 0.35

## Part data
C1 C5 C18 C25 C37: library part CMP-0007040-4, "CAP, CERM, 1 uF, 25 V, +/- 10%, X7R, 0603", Cap_Case=0603, Manufacturer=TDK, Supplier Part Number 1=445-5956-1-ND, TempCo=X7R, Tolerance_%=10%, Value1=Unknown, Value2=25V, ValueDisplayed=1uF
C2 C3 C4 C9 C11 C12 C14 C16 C17 C21 C28 C35 C118 C121 C122: library part CMP-0082267-1, "CAP, CERM, 22 µF, 25 V,+/- 10%, X7R, 1210", Cap_Case=1210, Manufacturer=Yageo, Supplier Part Number 1=311-2032-2-ND, TempCo=X7R, Tolerance_%=10%, Value1="0.001 ohm", Value2=25V, ValueDisplayed=22µF
C6: library part CMP-0006344-2, "CAP, CERM, 2200 pF, 50 V, +/- 5%, X7R, 0402", Cap_Case=0402, Manufacturer="Samsung Electro-Mechanics", Supplier Part Number 1=1276-1532-1-ND, TempCo=X7R, Tolerance_%=5%, Value1=Unknown, Value2=50V, ValueDisplayed=2200pF
C7: library part CMP-0006688-2, "CAP, CERM, 3300 pF, 50 V, +/- 10%, X7R, 0402", Cap_Case=0402, Manufacturer=MuRata, Supplier Part Number 1=490-3248-1-ND, TempCo=X7R, Tolerance_%=10%, Value1=Unknown, Value2=50V, ValueDisplayed=3300pF
C8 C10 C13 C15 C19 C29 C33 C40 C46 C47 C56 C57 C58 C59 C60 C63 C66 C67 C68 C69 C70 C71 C72 C73 C74 C75 C76 C77 C78 C79 C80 C81 C82 C83 C84 C85 C86 C87 C90 C92 C114 C115 C116 C119 C120 C123 C124 C125 C127 C128 C129 C130 C131 C132 C133 C134 C135 C139 C140 C145 C147 C148 C149 C162: library part CMP-0860555-1, "CAP, CERM, 0.1 µF, 25 V,+/- 10%, X7R, 0402", Cap_Case=0402, Manufacturer=Yageo, TempCo=X7R, Tolerance_%=10%, Value2=25V, ValueDisplayed=0.1µF
C20 C24 C32 C36 C38 C49 C52 C53 C150 C151 C152 C153 C154 C155 C158 C160: library part CMP-0052806-1, "WCAP-CSGP Multilayer Ceramic Chip Capacitor, General Purpose, size 0402, X7R, 10nF, 25VDC", Capacitance Tolerance=+/-10%, Insulation Resistance=10GOhm, Manufacturer="Wurth Elektronik", Operating Temperature Max=125°C, Operating Temperature Min=-55°C, Rated Voltage (DC)=25V
C22 C26 C31 C39: library part CMP-0008802-2, "CAP, CERM, 10 uF, 50 V, +/- 10%, X7R, 1206", Cap_Case=1206, Manufacturer=Samsung, Supplier Part Number 1=1276-6767-1-ND, TempCo=X7R, Tolerance_%=10%, Value1=Unknown, Value2=50V, ValueDisplayed=10uF
C23: library part CMP-0006488-2, "CAP, CERM, 6.8 pF, 50 V, +/- 5%, C0G/NP0, 0402", Cap_Case=0402, Manufacturer=MuRata, Supplier Part Number 1=81-GRM1555C1H6R8CA1D, TempCo=C0G/NP0, Tolerance_%=5%, Value1=Unknown, Value2=50V, ValueDisplayed=6.8pF
C27: library part CMP-0006293-2, "CAP, CERM, 0.22 uF, 16 V, +/- 10%, X7R, 0402", Cap_Case=0402, Manufacturer=TDK, Supplier Part Number 1=445-5936-1-ND, TempCo=X7R, Tolerance_%=10%, Value1=Unknown, Value2=16V, ValueDisplayed=0.22uF
C30: library part CMP-0006482-2, "CAP, CERM, 5.6 pF, 50 V, +/- 5%, C0G/NP0, 0402", Cap_Case=0402, Manufacturer=MuRata, Supplier Part Number 1=14T3297, TempCo=C0G/NP0, Tolerance_%=5%, Value1=Unknown, Value2=50V, ValueDisplayed=5.6pF
C34 C137 C142: library part CMP-0115376-1, "WCAP-CSGP Multilayer Ceramic Chip Capacitor, General Purpose, size 0402, X7R, 4.7nF, 50VDC", Capacitance Tolerance=+/-10%, Insulation Resistance=10GOhm, Manufacturer="Wurth Elektronik", Operating Temperature Max=125°C, Operating Temperature Min=-55°C, Rated Voltage (DC)=50V
C41 C54 C55 C61 C62 C65: library part CMP-0007007-5, "CAP, CERM, 10 uF, 25 V, +/- 20%, X5R, 0603", Cap_Case=0603, Manufacturer=TDK, Supplier Part Number 1=445-9015-1-ND, TempCo=X5R, Tolerance_%=20%, Value1="0.004639 ohm", Value2=25V, ValueDisplayed=10uF
C42: library part CMP-0006551-2, "CAP, CERM, 0.47 uF, 6.3 V, +/- 10%, X5R, 0402", Cap_Case=0402, Manufacturer=MuRata, Supplier Part Number 1=490-3266-1-ND, TempCo=X5R, Tolerance_%=10%, Value1=Unknown, Value2=6.3V, ValueDisplayed=0.47uF
C43 C44 C163 C164: library part CMP-0006415-2, "CAP, CERM, 12 pF, 50 V, +/- 5%, C0G/NP0, 0402", Cap_Case=0402, Manufacturer=MuRata, Supplier Part Number 1=14T3292, TempCo=C0G/NP0, Tolerance_%=5%, Value1=Unknown, Value2=50V, ValueDisplayed=12pF
C45: library part CMP-0104471-1, "WCAP-CSGP Multilayer Ceramic Chip Capacitor, General Purpose, size 0402, X5R, 4.7µF, 6.3VDC", Capacitance Tolerance=+/-20%, Insulation Resistance=0.02GOhm, Manufacturer="Wurth Elektronik", Operating Temperature Max=85°C, Operating Temperature Min=-55°C, Rated Voltage (DC)=6.3V
C48 C98 C108 C156 C157 C159 C161: library part CMP-0006300-2, "CAP, CERM, 1 uF, 10 V, +/- 10%, X7S, 0402", Cap_Case=0402, Manufacturer=TDK, Supplier Part Number 1=445-9116-1-ND, TempCo=X7S, Tolerance_%=10%, Value1="0.011416 ohm", Value2=10V, ValueDisplayed=1uF
C50 C51: library part CMP-0115372-1, "WCAP-CSGP Multilayer Ceramic Chip Capacitor, General Purpose, size 0402, X7R, 1nF, 50VDC", Capacitance Tolerance=+/-10%, Insulation Resistance=10GOhm, Manufacturer="Wurth Elektronik", Operating Temperature Max=125°C, Operating Temperature Min=-55°C, Rated Voltage (DC)=50V
C64: library part CMP-0007890-2, "CAP, CERM, 22 uF, 10 V, +/- 20%, X7S, 0805", Cap_Case=0805, Manufacturer=TDK, Supplier Part Number 1=445-14560-1-ND, TempCo=X7S, Tolerance_%=20%, Value1="0.00205 ohm", Value2=10V, ValueDisplayed=22uF
C88 C89: library part CMP-0105275-1, "WCAP-CSRF Multilayer Ceramic Chip Capacitor, High Frequency, size 0402, NP0 Class I, 12pF, 50VDC", Capacitance Tolerance=+/-2%, Insulation Resistance=10GOhm, Manufacturer="Wurth Elektronik", Operating Temperature Max=125°C, Operating Temperature Min=-55°C, Rated Voltage (DC)=50V
C91: library part CMP-0006453-2, "CAP, CERM, 300 pF, 50 V, +/- 5%, C0G/NP0, 0402", Cap_Case=0402, Manufacturer=MuRata, TempCo=C0G/NP0, Tolerance_%=5%, Value1=Unknown, Value2=50V, ValueDisplayed=300pF
C93 C104 C117 C144 C146: library part CMP-0006196-2, "CAP, CERM, 100 pF, 50 V, +/- 1%, C0G/NP0, 0402", Cap_Case=0402, Manufacturer=AVX, Supplier Part Number 1=478-3658-1-ND, TempCo=C0G/NP0, Tolerance_%=1%, Value1=Unknown, Value2=50V, ValueDisplayed=100pF
C94 C111: library part CMP-0006275-2, "CAP, CERM, 2.2 uF, 16 V, +/- 10%, X5R, 0402", Cap_Case=0402, Manufacturer=TDK, Supplier Part Number 1=445-9085-1-ND, TempCo=X5R, Tolerance_%=10%, Value1=Unknown, Value2=16V, ValueDisplayed=2.2uF
C95 C112: library part CMP-0104158-1, "WCAP-CSGP Multilayer Ceramic Chip Capacitor, General Purpose, size 0402, NP0, 68pF, 50VDC", Capacitance Tolerance=+/-5%, Insulation Resistance=10GOhm, Manufacturer="Wurth Elektronik", Operating Temperature Max=125°C, Operating Temperature Min=-55°C, Rated Voltage (DC)=50V
C96 C113: library part CMP-0053498-1, "WCAP-CSGP Multilayer Ceramic Chip Capacitor, General Purpose, size 0402, X7R, 680pF, 50VDC", Capacitance Tolerance=+/-10%, Insulation Resistance=10GOhm, Manufacturer="Wurth Elektronik", Operating Temperature Max=125°C, Operating Temperature Min=-55°C, Rated Voltage (DC)=50V
C97 C107: library part CMP-0860564-1, "CAP, CERM, 2700 pF, 50 V,+/- 10%, X7R, 0402", Cap_Case=0402, Manufacturer="Samsung Electro-Mechanics", TempCo=X7R, Tolerance_%=10%, Value2=50V, ValueDisplayed=2700pF
C99 C109: library part CMP-0053546-1, "WCAP-CSGP Multilayer Ceramic Chip Capacitor, General Purpose, size 0402, X7R, 1.5nF, 50VDC", Capacitance Tolerance=+/-10%, Insulation Resistance=10GOhm, Manufacturer="Wurth Elektronik", Operating Temperature Max=125°C, Operating Temperature Min=-55°C, Rated Voltage (DC)=50V
C100 C110: library part CMP-0053550-1, "WCAP-CSGP Multilayer Ceramic Chip Capacitor, General Purpose, size 0402, X7R, 2.2nF, 50VDC", Capacitance Tolerance=+/-10%, Insulation Resistance=10GOhm, Manufacturer="Wurth Elektronik", Operating Temperature Max=125°C, Operating Temperature Min=-55°C, Rated Voltage (DC)=50V
C101 C102: library part CMP-0104156-1, "WCAP-CSGP Multilayer Ceramic Chip Capacitor, General Purpose, size 0402, NP0, 33pF, 50VDC", Capacitance Tolerance=+/-5%, Insulation Resistance=10GOhm, Manufacturer="Wurth Elektronik", Operating Temperature Max=125°C, Operating Temperature Min=-55°C, Rated Voltage (DC)=50V
C103: library part CMP-0112442-1, "WCAP-CSRF Multilayer Ceramic Chip Capacitor, High Frequency, size 0402, NP0 Class I, 22pF, 50VDC", Capacitance Tolerance=+/-5%, Insulation Resistance=10GOhm, Manufacturer="Wurth Elektronik", Operating Temperature Max=125°C, Operating Temperature Min=-55°C, Rated Voltage (DC)=50V
C105: library part CMP-0065518-1, "WCAP-CSRF Multilayer Ceramic Chip Capacitor, High Frequency, size 0402, NP0 Class I, 27pF, 50VDC", Capacitance Tolerance=+/-5%, Insulation Resistance=10GOhm, Manufacturer="Wurth Elektronik", Operating Temperature Max=125°C, Operating Temperature Min=-55°C, Rated Voltage (DC)=50V
C106: library part CMP-0114900-1, "WCAP-CSGP Multilayer Ceramic Chip Capacitor, General Purpose, size 0402, NP0, 47pF, 50VDC", Capacitance Tolerance=+/-5%, Insulation Resistance=10GOhm, Manufacturer="Wurth Elektronik", Operating Temperature Max=125°C, Operating Temperature Min=-55°C, Rated Voltage (DC)=50V
C126: library part CMP-0115492-1, "WCAP-CSGP Multilayer Ceramic Chip Capacitor, General Purpose, size 0603, X7R, 330nF, 50VDC", Capacitance Tolerance=+/-10%, Insulation Resistance=1.5GOhm, Manufacturer="Wurth Elektronik", Operating Temperature Max=125°C, Operating Temperature Min=-55°C, Rated Voltage (DC)=50V
C136 C138 C141 C143: library part CMP-0006241-2, "CAP, CERM, 20 pF, 50 V, +/- 5%, C0G/NP0, 0402", Cap_Case=0402, Manufacturer=Kemet, Supplier Part Number 1=399-7773-1-ND, TempCo=C0G/NP0, Tolerance_%=5%, Value1=Unknown, Value2=50V, ValueDisplayed=20pF
D1 D33 D34: library part CMP-0005899-4, "Diode, Zener, 5.1 V, 300 mW, SOD-523", Manufacturer="Diodes Inc.", Power_W=300mW, Value1=0.3W
D2 D4 D20: library part CMP-0002947-3, "LED, Red, SMD", Color=Red, Manufacturer="Wurth Elektronik", Power_TotalModule=72mW, Value1=0.072W, Value2=2V
D3: library part CMP-0029150-2, "Diode, Switching, 200 V, 0.2 A, AEC-Q101, SOD-323", Manufacturer="ON Semiconductor", Value1=0.2A, Value2=1.25V
D5 D6 D13 D22 D25 D27 D28 D39: library part CMP-0002894-2, "LED, Green, SMD", Color=green, Manufacturer="Wurth Elektronik", Value1=W, Value2=2V
D7 D11: library part CMP-0001466-1, "Diode 40 V 2A Surface Mount SOD-123FL", Digikey Part Number=3757-SS2040FL_R1_00001CT-ND, Forward Current=2A, Manufacturer=Panjit, Max Surge Forward Current=50A, Mouser Part Number=241-SS2040FLR100001, Operating Temperature Range="-50°C to +150°C", Peak Reverse Current=100uA
D8 D10: library part CMP-0028526-2, "Diode, Schottky, 40 V, 0.5 A, SOD-123", Manufacturer="ON Semiconductor", Value1=0.5A, Value2=0.51V
D9 D12: library part CMP-0076928-2, "Diode, Schottky, 40 V, 0.35 A, SOD-323", Manufacturer="Micro Commercial Components", Value1=0.35A, Value2=0.6V
D14 D19 D21 D23: library part CMP-0124220-1, "Bidirectional TVS Diodes in SOD-323 Package", Breakdown Voltage=13.2V, Clamping Voltage=26V, Digikey Part Number=296-TSD12CDYFRCT-ND, Manufacturer="Texas Instruments", Mouser Part Number=595-TSD12CDYFR, Operating Temperature Range="-55°C to +150°C", ValueDisplayed=6.5pF
D15 D16 D24 D26 D29 D30 D36 D37: library part CMP-0122929-1, "One-channel unidirectional device for 3.3V surge protection in SOD-323 package", Breakdown Voltage=4.5V, Clamping Voltage=6.3V, Digikey Part Number=296-ESDS311DYFRCT-ND, Manufacturer="Texas Instruments", Mouser Part Number=595-ESDS311DYFR, Operating Temperature Range="-40°C to +125°C", ValueDisplayed=4.5pF
D17: library part CMP-0126831-1, "RF Diode PIN - Single 30V 100 mA EMD2", Digikey Part Number=846-RN242SMT2RCT-ND, Forward Current=100mA, Manufacturer=Rohm, Mouser Part Number=755-RN242SMT2R, Operating Temperature Range="to +150°C", Peak Reverse Current=0.1uA, ValueDisplayed=0.35pF
D18 D35: library part CMP-0125981-1, "23V Clamp 18A (8/20µs) Ipp Tvs Diode Surface Mount SOD-323", Breakdown Voltage=12.7V, Clamping Voltage=23V, Digikey Part Number=296-TSD12DYFRCT-ND, Manufacturer="Texas Instruments", Mouser Part Number=595-TSD12DYFR, Operating Temperature Range="-55°C to +150°C", ValueDisplayed=12pF
D31 D32: library part CMP-0124250-1, "15V 13A bidirectional surge-protection diode", Manufacturer="Texas Instruments", Operating Temperature Range=to, PartNumber=TSD15CDYFR
D38: library part CMP-0124839-1, "Amber 605nm LED Indication - Discrete 2V 0603 (1608 Metric)", Color=Amber, Digikey Part Number=732-150060AS75000CT-ND, Forward Current=20mA, Manufacturer="Wurth Electronics", Mouser Part Number=710-150060AS75000, Operating Temperature Range="-40°C to +85°C", Power_TotalModule=72mW
F1: library part CMP-0003461-2, "Fuse, 1.5 A, 50VAC/VDC, SMD", Irating_A=1.5A, Manufacturer=Littelfuse, Supplier Part Number 1=F1611TR-ND
FB1: library part CMP-03913-52738340-1, "74279220601 Ferrite Beads Multi-Layer High Current 600Ohm 25% 100MHz 2.1A 0.08Ohm DCR 0805 Automotive T/R", Case Code (Imperial)=0805, Case Code (Metric)=2012, Current Rating=2.1A, DC Resistance (DCR)=43mΩ, Manufacturer="Wurth Elektronik", Max Operating Temperature=125°C, Min Operating Temperature=-55°C, Test Frequency=100MHz, Tolerance=25%
FID1 FID2 FID3 FID4 FID5 FID6: library part CMP-0077181-1, "Fiducial mark.  There is nothing to buy or mount.", Manufacturer=N/A
J1 J7 J10 J21 J22 J23: library part CMP-0093089-2, "2 Position Wire to Board Terminal Block Horizontal with Board 0.138\" (3.50mm) Through Hole", Current_A=10A, Digikey Part Number=732-691214110002S-ND, Manufacturer=Wurth, Mouser Part Number=710-691214110002S, Operating Temperature Range="-30°C to +120°C", Voltage_V=300V
J2 J6 J12: library part CMP-0054794-2, "Header, 2.54 mm, 2x1, Gold, TH", Color=Black, Manufacturer="Wurth Elektronik", Supplier Part Number 1=732-5315-ND
J3 J5 J8 J9 J29 J32: library part CMP-0054796-4, "Header, 2.54 mm, 3x1, Gold, TH", Manufacturer="Wurth Elektronik", Supplier Part Number 1=732-5316-ND
J4 J11 J13 J14 J15 J16 J17 J18 J19 J20 J30 J31: library part CMP-0124724-1, "3 Position Wire to Board Terminal Block Horizontal with Board 0.138\" (3.50mm) Through Hole", Current_A=10A, Digikey Part Number=732-691214110003S-ND, Manufacturer=Wurth, Mouser Part Number=710-691214110003S, Operating Temperature Range="-30°C to +120°C", Voltage_V=300V
J24: library part CMP-0097334-1, "Connector Header Through Hole 14 position 0.100\" (2.54mm)", Current_A=3A, Digikey Part Number=732-5298-ND, Manufacturer="Wurth Electronics", Mouser Part Number=710-61301421121, Operating Temperature Range="-40°C to +105°C", Voltage_V=250V
J25: library part CMP-0123499-1, "USB-C (USB TYPE-C) USB 2.0 Receptacle Connector 24 (16+8 Dummy) Position Surface Mount, Right Angle; Through Hole", Current_A=5A, Digikey Part Number=2073-USB4215-03-ACT-ND, Manufacturer=GCT, Mouser Part Number=640-USB4215-03-A, Operating Temperature Range="-25°C to +85°C", Voltage_V=48V
J26: library part CMP-0124771-1, "Connector Header Through Hole 18 position 0.100\" (2.54mm)", Current_A=3A, Digikey Part Number=732-5300-ND, Manufacturer=Wurth, Mouser Part Number=710-61301821121, Operating Temperature Range="-40°C to +105°C", Voltage_V=250V
J27: library part CMP-0074852-1, "Receptacle, 2.54mm, 5X2, Gold, TH", Color=Black, Current_A=4.7A, Manufacturer=Samtec, Supplier Part Number 1=SAM1208-05-ND, Voltage_V=465V
J28: library part CMP-0126816-1, "30 Position Receptacle Connector 0.100\" (2.54mm) Through Hole Gold", Current_A=4.7A, Digikey Part Number=SAM1208-15-ND, Manufacturer=Samtec, Mouser Part Number=200-SSW11501GD, Operating Temperature Range="-55°C to +125°C", Voltage_V=655V
L1 L3: library part CMP-0003141-1, "Ferrite Bead, 600 ohm @ 100 MHz, 2.5 A, 1206", Manufacturer="Wurth Elektronik", Supplier Part Number 1=732-6133-1-ND, Value1="0.038 ohm", Value2=2.5A, ValueDisplayed="600 ohm"
L2: library part CMP-0063928-1, "Inductor, Shielded Drum Core, Superflux, 4.7 uH, 6 A, 0.02 ohm, SMD", Manufacturer="Wurth Elektronik", Supplier Part Number 1=732-1153-1-ND, Value1="0.02 ohm", Value2=6A, ValueDisplayed=4.7uH
L4 L7: library part CMP-0003140-1, "Ferrite Bead, 280 ohm @ 100 MHz, 3.5 A, 1206", Manufacturer="Wurth Elektronik", Supplier Part Number 1=732-6132-1-ND, Value1="0.022 ohm", Value2=3.5A, ValueDisplayed="280 ohm"
L5: library part CMP-0064107-1, "Inductor, Shielded Drum Core, Powdered Iron, 3.3 uH, 6 A, 0.019 ohm, SMD", Manufacturer="Wurth Elektronik", Supplier Part Number 1=732-3353-1-ND, Value1="0.019 ohm", Value2=6A, ValueDisplayed=3.3uH
L6 L8: library part CMP-0063804-1, "Inductor, Shielded Drum Core, Ferrite, 10 uH, 1 A, 0.12 ohm, SMD", Manufacturer="Wurth Elektronik", Supplier Part Number 1=732-1025-1-ND, Value1="0.12 ohm", Value2=1A, ValueDisplayed=10uH
L9: library part CMP-0003197-2, "Ferrite Bead, 600 ohm @ 100 MHz, 1 A, 0603", Manufacturer="Wurth Elektronik", Supplier Part Number 1=732-1593-1-ND, Value1="0.2 ohm", Value2=1A, ValueDisplayed="600 ohm"
L10: library part CMP-0124832-1, "2 Line Common Mode Choke Surface Mount 360mA DCR 500mOhm", Digikey Part Number=490-7981-1-ND, Manufacturer=Murata, Mouser Part Number=81-DLW43SH110XK2L, Operating Temperature Range="-40°C to +125°C", Test Frequency=100kHz, Tolerance_%=+50/-30%
L11: library part CMP-0003136-1, "Ferrite Bead, 600 ohm @ 100 MHz, 2.1 A, 0805", Manufacturer="Wurth Elektronik", Supplier Part Number 1=732-6126-1-ND, Value1="0.043 ohm", Value2=2.1A, ValueDisplayed="600 ohm"
L12 L14: library part CMP-0003312-1, "Ferrite Bead, 220 ohm @ 100 MHz, 0.45 A, 0402", Manufacturer=MuRata, Supplier Part Number 1=490-5178-1-ND, Value1="0.29 ohm", Value2=0.45A, ValueDisplayed="220 ohm"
